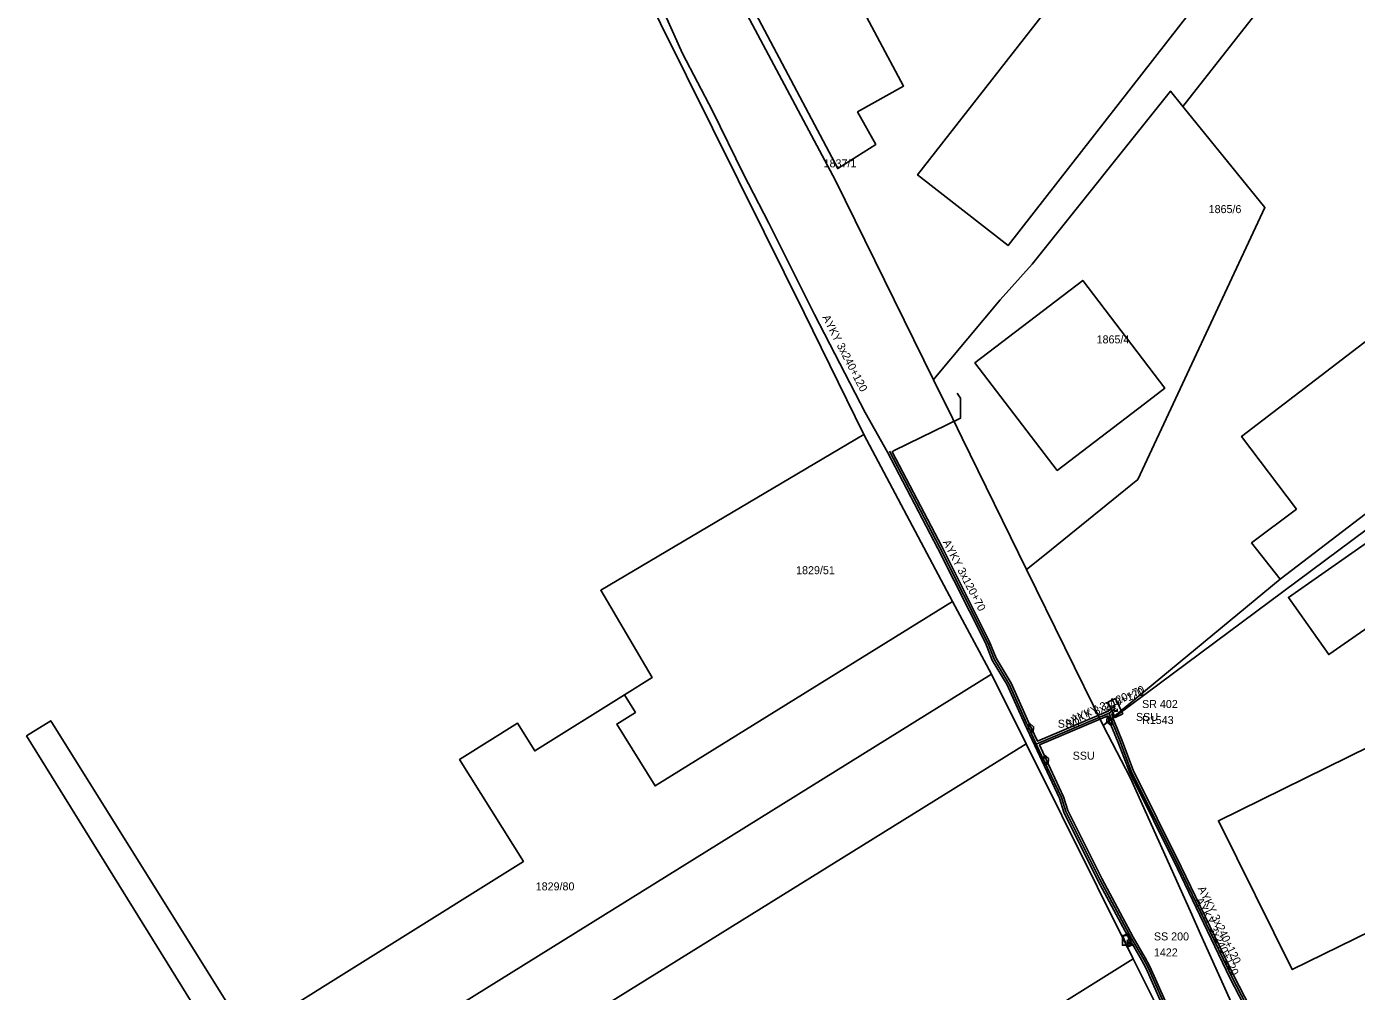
# Model space of a CAD drawing. Extents: x -793400 to -756198, y -1074141 to -1042963.
# Drawn here: x -783797.2 to -783672.6, y -1065107.5 to -1065017.1 of the extents above; entities that cross this region are included whole.
import ezdxf

# ---------------------------------------------------------------- set-up
doc = ezdxf.new("R2010")
doc.units = 0
for name, color, linetype in [('Parcela', 7, 'Continuous'), ('Popiskový text - Parcela', 7, 'Continuous'), ('Popiskový text - Přípojková skříň nn - SJZ', 7, 'Continuous'), ('Popiskový text - Přípojková skříň nn - Typ', 7, 'Continuous'), ('Popiskový text - Rozpojovací skříň nn - SJZ', 7, 'Continuous'), ('Popiskový text - Rozpojovací skříň nn - Typ', 7, 'Continuous'), ('Popiskový text - Spojka nn - Typ', 7, 'Continuous'), ('Popiskový text - Vedení nn kabelové', 7, 'Continuous'), ('Skříň', 7, 'Continuous'), ('Spojka nn', 7, 'Continuous'), ('Spojnice nn', 7, 'Continuous'), ('Stavební objekt', 7, 'Continuous'), ('Vedení nn kabelové', 7, 'Continuous')]:
    doc.layers.add(name, color=color, linetype=linetype)

msp = doc.modelspace()

# ---------------------------------------------------------------- linework, layer by layer
at = {"layer": 'Parcela'}
for points in [[(-783679.72, -1065068.87), (-783696.3, -1065082.59), (-783703.49, -1065067.95), (-783701.82, -1065066.6), (-783693.07, -1065059.53), (-783681.16, -1065034.03), (-783688.84, -1065024.56), (-783667.93, -1064997.88), (-783659.12, -1064988.88), (-783657.73, -1064987.44), (-783656.18, -1064989.41), (-783657.28, -1064990.53), (-783648.71, -1064998.93), (-783633.99, -1065017.67), (-783634.29, -1065017.9), (-783683.34, -1065055.48), (-783678.2, -1065062.3), (-783682.41, -1065065.47)], [(-783685.82, -1065012.69), (-783694.29, -1065006.1), (-783713.7, -1065030.98), (-783705.23, -1065037.6)], [(-783626.47, -1065028.12), (-783679.72, -1065068.87), (-783682.41, -1065065.47), (-783678.2, -1065062.3), (-783683.34, -1065055.48), (-783634.29, -1065017.9), (-783633.99, -1065017.67), (-783626.05, -1065027.79)], [(-783701.82, -1065066.6), (-783703.49, -1065067.95), (-783709.53, -1065055.65), (-783710.41, -1065053.85), (-783712.22, -1065050.17), (-783712.02, -1065049.94), (-783705.96, -1065042.68), (-783702.98, -1065039.35), (-783690, -1065023.13), (-783688.84, -1065024.56), (-783681.16, -1065034.03), (-783693.07, -1065059.53)], [(-783624.81, -1065029.37), (-783696.3, -1065082.59), (-783679.72, -1065068.87), (-783626.47, -1065028.12), (-783626.05, -1065027.79)], [(-783624.81, -1065029.37), (-783608.24, -1065050.49), (-783609.02, -1065051.01), (-783614.97, -1065042.05), (-783620.25, -1065045.55), (-783614.53, -1065054.22), (-783645.96, -1065074.99), (-783640.19, -1065083.64), (-783609.28, -1065062.42), (-783602.2, -1065072.93), (-783596.89, -1065069.32), (-783607.37, -1065053.5), (-783606.59, -1065052.98), (-783598.14, -1065065.66), (-783595.45, -1065069.7), (-783618.75, -1065083), (-783634.61, -1065095.52), (-783641.16, -1065099.33), (-783680.77, -1065116.4), (-783687.19, -1065102.12), (-783688.13, -1065100.02), (-783693.78, -1065087.45), (-783696.3, -1065082.59)], [(-783692.44, -1065052.42), (-783690.53, -1065050.96), (-783698.23, -1065040.86), (-783708.33, -1065048.58), (-783700.62, -1065058.67)], [(-783692.44, -1065052.42), (-783700.62, -1065058.67), (-783708.33, -1065048.58), (-783698.23, -1065040.86), (-783690.53, -1065050.96)], [(-783710.42, -1065070.95), (-783738.3, -1065088.24), (-783741.89, -1065082.45), (-783740.15, -1065081.36), (-783741.18, -1065079.7), (-783738.57, -1065078.08), (-783743.4, -1065069.9), (-783718.74, -1065055.31)], [(-783667.38, -1065070.51), (-783671.15, -1065065.12), (-783678.96, -1065070.57), (-783675.18, -1065075.93)], [(-783667.38, -1065070.51), (-783675.18, -1065075.93), (-783678.96, -1065070.57), (-783671.15, -1065065.12)], [(-783706.78, -1065077.78), (-783763.85, -1065113.27), (-783759.96, -1065119.35), (-783776.33, -1065129.79), (-783779.45, -1065113.42), (-783779.79, -1065111.66), (-783782.26, -1065107.68), (-783797.2, -1065083.56), (-783794.93, -1065082.14), (-783776.57, -1065111.53), (-783750.64, -1065095.32), (-783756.62, -1065085.78), (-783751.21, -1065082.35), (-783749.58, -1065084.96), (-783741.18, -1065079.7), (-783740.15, -1065081.36), (-783741.89, -1065082.45), (-783738.3, -1065088.24), (-783710.42, -1065070.95)], [(-783646.12, -1065089.53), (-783653.08, -1065075.54), (-783685.51, -1065091.5), (-783678.6, -1065105.46)], [(-783646.12, -1065089.53), (-783678.6, -1065105.46), (-783685.51, -1065091.5), (-783653.08, -1065075.54)], [(-783693.49, -1065104.44), (-783689.14, -1065113.18), (-783698.37, -1065116.59), (-783701.76, -1065109.61), (-783706.21, -1065112.39), (-783713.05, -1065116.67), (-783743.22, -1065135.54), (-783740.24, -1065140.31), (-783743.33, -1065142.34), (-783746.36, -1065137.5), (-783750.65, -1065140.19), (-783764.55, -1065148.9), (-783776.33, -1065129.79), (-783759.96, -1065119.35), (-783763.85, -1065113.27), (-783706.78, -1065077.78), (-783703.53, -1065084.3)]]:
    msp.add_lwpolyline(points, close=True, dxfattribs=at)
for points in [[(-783667.93, -1064997.88), (-783688.84, -1065024.56), (-783690, -1065023.13), (-783702.98, -1065039.35), (-783705.96, -1065042.68), (-783712.02, -1065049.94), (-783712.22, -1065050.17), (-783721.39, -1065031.49), (-783743.49, -1064990.04)], [(-783743.49, -1064990.04), (-783721.39, -1065031.49), (-783712.22, -1065050.17), (-783710.41, -1065053.85), (-783709.53, -1065055.65), (-783703.49, -1065067.95), (-783696.3, -1065082.59), (-783693.78, -1065087.45), (-783688.13, -1065100.02), (-783687.19, -1065102.12), (-783680.77, -1065116.4), (-783681, -1065116.57), (-783682.63, -1065117.8), (-783685.7, -1065120.1), (-783686.08, -1065119.34), (-783689.14, -1065113.18), (-783693.49, -1065104.44), (-783703.53, -1065084.3), (-783706.78, -1065077.78), (-783710.42, -1065070.95), (-783718.74, -1065055.31), (-783724.35, -1065043.92), (-783728.08, -1065036.33), (-783742.64, -1065007.02)], [(-783733.81, -1065006.54), (-783721.18, -1065030.38), (-783717.63, -1065028.12), (-783719.33, -1065025.07), (-783715.02, -1065022.66), (-783724.9, -1065004.13)]]:
    msp.add_lwpolyline(points, dxfattribs=at)
at = {"layer": 'Skříň'}
for points in [[(-783694.47, -1065081.48), (-783695.16, -1065080.06), (-783695.87, -1065080.4), (-783695.18, -1065081.82)], [(-783694.08, -1065103.35), (-783694.55, -1065102.32), (-783694.04, -1065102.09), (-783693.57, -1065103.12)], [(-783694.47, -1065102.35), (-783694.06, -1065103.27), (-783693.65, -1065103.09), (-783694.06, -1065102.17)]]:
    msp.add_lwpolyline(points, close=True, dxfattribs=at)
at = {"layer": 'Spojka nn'}
for points in [[(-783695.55, -1065082.61), (-783695.51, -1065082.05), (-783695.93, -1065081.68), (-783695.97, -1065082.24)], [(-783702.87, -1065083.25), (-783702.84, -1065082.69), (-783703.26, -1065082.32), (-783703.3, -1065082.88)], [(-783701.47, -1065086.24), (-783701.44, -1065085.68), (-783701.86, -1065085.32), (-783701.9, -1065085.88)]]:
    msp.add_lwpolyline(points, close=True, dxfattribs=at)
at = {"layer": 'Spojnice nn'}
for p, q in [((-783695.17, -1065080.94), (-783695.74, -1065081.41)), ((-783695.74, -1065081.41), (-783702.6, -1065084.32)), ((-783695.74, -1065081.41), (-783695.55, -1065082.08)), ((-783702.6, -1065084.32), (-783703.26, -1065082.86)), ((-783701.84, -1065085.92), (-783702.6, -1065084.32)), ((-783693.66, -1065102.53), (-783694.06, -1065102.72))]:
    msp.add_line(p, q, dxfattribs=at)
for points in [[(-783703.26, -1065082.86), (-783703.49, -1065082.36), (-783705.13, -1065078.69), (-783706.53, -1065076.36), (-783707.17, -1065074.76), (-783711.62, -1065065.89), (-783716.35, -1065056.87)], [(-783695.55, -1065082.08), (-783694.73, -1065084.09), (-783693.68, -1065086.85), (-783689.18, -1065095.9), (-783684.26, -1065106.14), (-783680.29, -1065113.8), (-783679.9, -1065114.71), (-783679.3, -1065114.81)], [(-783693.66, -1065102.53), (-783696.62, -1065097.02), (-783699.82, -1065090.63), (-783700.23, -1065089.33), (-783701.84, -1065085.92)], [(-783678.98, -1065131.76), (-783681.62, -1065126.92), (-783682.33, -1065124.98), (-783683.82, -1065122.09), (-783685.07, -1065119.39), (-783686.1, -1065117.51), (-783689.26, -1065111.69), (-783692.11, -1065105.25), (-783692.55, -1065104.45), (-783693.66, -1065102.53)]]:
    msp.add_lwpolyline(points, dxfattribs=at)
at = {"layer": 'Stavební objekt'}
for points in [[(-783626.47, -1065028.12), (-783679.72, -1065068.87), (-783682.41, -1065065.47), (-783678.2, -1065062.3), (-783683.34, -1065055.48), (-783634.29, -1065017.9)], [(-783692.44, -1065052.42), (-783700.62, -1065058.67), (-783708.33, -1065048.58), (-783698.23, -1065040.86), (-783690.53, -1065050.96)], [(-783710.42, -1065070.95), (-783738.3, -1065088.24), (-783741.89, -1065082.45), (-783740.15, -1065081.36), (-783741.18, -1065079.7), (-783738.57, -1065078.08), (-783743.4, -1065069.9), (-783718.74, -1065055.31)], [(-783667.38, -1065070.51), (-783675.18, -1065075.93), (-783678.96, -1065070.57), (-783671.15, -1065065.12)], [(-783646.12, -1065089.53), (-783678.6, -1065105.46), (-783685.51, -1065091.5), (-783653.08, -1065075.54)], [(-783750.65, -1065140.19), (-783764.55, -1065148.9), (-783776.33, -1065129.79), (-783759.96, -1065119.35), (-783703.53, -1065084.3), (-783693.49, -1065104.44), (-783701.76, -1065109.61), (-783706.21, -1065112.39), (-783713.05, -1065116.67), (-783743.22, -1065135.54), (-783746.36, -1065137.5)]]:
    msp.add_lwpolyline(points, close=True, dxfattribs=at)
at = {"layer": 'Vedení nn kabelové'}
for points in [[(-783694.06, -1065102.72), (-783693.96, -1065103.18), (-783694.51, -1065103.18), (-783694.51, -1065102.27), (-783694.03, -1065102.27), (-783696.8, -1065097.11), (-783700.01, -1065090.71), (-783700.42, -1065089.4), (-783703.67, -1065082.44), (-783705.31, -1065078.78), (-783706.71, -1065076.45), (-783707.35, -1065074.84), (-783711.8, -1065065.98), (-783716.53, -1065056.97), (-783718.63, -1065053.25), (-783723.36, -1065044.05), (-783727.66, -1065035.49), (-783730.02, -1065030.92), (-783732.94, -1065024.97), (-783735.73, -1065019.61), (-783738.18, -1065014.14)], [(-783710.01, -1065051.44), (-783709.7, -1065051.9), (-783709.67, -1065053.77), (-783715.89, -1065056.8), (-783716.09, -1065056.94), (-783711.44, -1065065.8), (-783706.99, -1065074.68), (-783706.35, -1065076.27), (-783704.95, -1065078.6), (-783703.31, -1065082.28), (-783703.07, -1065082.79)], [(-783703.07, -1065082.79), (-783702.48, -1065084.05), (-783695.84, -1065081.24), (-783695.27, -1065080.77), (-783695.27, -1065081.21), (-783695.01, -1065081.21), (-783695.01, -1065081.03)], [(-783679.3, -1065114.81), (-783679.27, -1065114.61), (-783679.76, -1065114.53), (-783680.11, -1065113.71), (-783684.08, -1065106.05), (-783689, -1065095.81), (-783693.5, -1065086.77), (-783694.54, -1065084.02), (-783695.36, -1065082.01), (-783695.51, -1065081.48), (-783695.22, -1065081.24), (-783694.99, -1065081.24), (-783694.99, -1065081.03)], [(-783695.74, -1065082.15), (-783695.87, -1065081.68), (-783702.28, -1065084.4), (-783701.67, -1065085.78)], [(-783695.74, -1065082.15), (-783694.92, -1065084.16), (-783693.86, -1065086.93), (-783689.36, -1065095.99), (-783684.44, -1065106.23), (-783680.47, -1065113.89), (-783680.04, -1065114.89), (-783679.33, -1065115.01), (-783679.3, -1065114.81)], [(-783689.08, -1065111.6), (-783691.93, -1065105.16), (-783692.38, -1065104.35), (-783693.49, -1065102.43), (-783696.44, -1065096.93), (-783699.63, -1065090.55), (-783700.04, -1065089.26), (-783701.67, -1065085.78)], [(-783679.61, -1065132.18), (-783679.61, -1065132.33), (-783679.94, -1065132.33), (-783679.94, -1065131.73), (-783679.53, -1065131.54), (-783679.36, -1065131.48), (-783681.8, -1065127), (-783682.51, -1065125.06), (-783684, -1065122.18), (-783685.25, -1065119.48), (-783686.28, -1065117.61), (-783689.44, -1065111.78), (-783692.29, -1065105.34), (-783692.72, -1065104.55), (-783693.57, -1065103.08), (-783693.7, -1065103.08), (-783693.78, -1065103.08), (-783694.06, -1065102.72)]]:
    msp.add_lwpolyline(points, dxfattribs=at)

# ---------------------------------------------------------------- texts
at = {"layer": 'Popiskový text - Parcela'}
for s, p in [('1837/1', (-783722.51, -1065030.27)), ('1865/6', (-783686.43, -1065034.56)), ('1865/4', (-783696.93, -1065046.77)), ('1829/51', (-783725.09, -1065068.4)), ('1829/80', (-783749.49, -1065098.03))]:
    msp.add_text(s, height=0.75, dxfattribs=at).set_placement(p)
at = {"layer": 'Popiskový text - Přípojková skříň nn - SJZ'}
msp.add_text('1422', height=0.75, dxfattribs=at).set_placement((-783691.56, -1065104.22))
at = {"layer": 'Popiskový text - Přípojková skříň nn - Typ'}
msp.add_text('SS 200', height=0.75, dxfattribs=at).set_placement((-783691.56, -1065102.72))
at = {"layer": 'Popiskový text - Rozpojovací skříň nn - SJZ'}
msp.add_text('R1543', height=0.75, dxfattribs=at).set_placement((-783692.67, -1065082.44))
at = {"layer": 'Popiskový text - Rozpojovací skříň nn - Typ'}
msp.add_text('SR 402', height=0.75, dxfattribs=at).set_placement((-783692.67, -1065080.94))
at = {"layer": 'Popiskový text - Spojka nn - Typ'}
for p in [(-783700.57, -1065082.79), (-783693.24, -1065082.15), (-783699.17, -1065085.78)]:
    msp.add_text('SSU', height=0.75, dxfattribs=at).set_placement(p)
at = {"layer": 'Popiskový text - Vedení nn kabelové'}
for s, rotation, p in [('AYKY 3x240+120', 297.2505, (-783722.66, -1065044.32)), ('AYKY 3x120+70', 297.6516, (-783711.37, -1065065.4)), ('AYKY 3x240+120', 22.9756, (-783699.74, -1065082.78)), ('AYKY 3x120+70', 22.9756, (-783699.16, -1065082.37)), ('AYKY 3x240+120', 295.6462, (-783687.47, -1065097.85)), ('AYKY 3x240+120', 295.6462, (-783687.68, -1065098.92))]:
    msp.add_text(s, height=0.75, rotation=rotation, dxfattribs=at).set_placement(p)

doc.saveas('drawing.dxf')
